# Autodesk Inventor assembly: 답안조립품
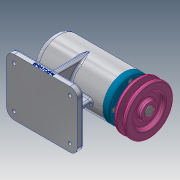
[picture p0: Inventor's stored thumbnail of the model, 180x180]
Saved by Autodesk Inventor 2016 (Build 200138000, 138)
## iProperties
Created: 2020-10
Part Number: 답안조립품
Document SubType Name: Assembly
Designer: user
Author: user
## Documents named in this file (12)
- C:\Users\user\Desktop\701004V1003\답안조립품.iam
- C:\Users\user\Desktop\701004V1003\1. 본체.ipt
- C:\Users\user\Desktop\701004V1003\베어링 51202.ipt
- C:\Users\user\Desktop\701004V1003\어댑터슬리브.ipt
- C:\Users\user\Desktop\701004V1003\축.ipt
- C:\Users\user\Desktop\701004V1003\볼트 M4.ipt
- C:\Users\user\Desktop\701004V1003\베어링 6004.ipt
- C:\Users\user\Desktop\701004V1003\커버.ipt
- C:\Users\user\Desktop\701004V1003\오일 실.ipt
- C:\Users\user\Desktop\701004V1003\키 5 x 5 x 16.ipt
- C:\Users\user\Desktop\701004V1003\V벨트풀리.ipt
- C:\Users\user\Desktop\701004V1003\멈춤나사 M3.ipt
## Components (2 placed, 2 different names)
1. 1. 본체:1
2. V벨트풀리:1
